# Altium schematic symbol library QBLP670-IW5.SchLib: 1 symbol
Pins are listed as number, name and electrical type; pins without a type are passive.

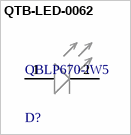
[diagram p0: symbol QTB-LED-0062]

## QTB-LED-0062
designator D?, comment QBLP670-IW5
LED WHITE CLEAR 2PLCC SMD; Manufacturer: QT Brightek (QTB); Luminous Intensity: 580mcd; Test Current: 5mA; Lens Color: Colorless; Lens Style: Oval with Flat Top; Forward Voltage: 2.7V; Viewing Angle: 120°
footprint QBLP670-IW5-MFG
pins: 1 ANODE (+), 2 CATHODE (-)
